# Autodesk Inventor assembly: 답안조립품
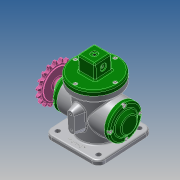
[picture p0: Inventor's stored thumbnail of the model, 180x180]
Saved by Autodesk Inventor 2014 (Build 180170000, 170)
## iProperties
Created: 2021-03
Part Number: 답안조립품
Document SubType Name: Assembly
Designer: kb542
Author: kb542
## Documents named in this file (19)
- C:\Users\kb542\Desktop\710306V1011\답안조립품.iam
- C:\Users\kb542\Desktop\710306V1011\E-링.ipt
- C:\Users\kb542\Desktop\710306V1011\덮개.ipt
- C:\Users\kb542\Desktop\710306V1011\뒤커버.ipt
- C:\Users\kb542\Desktop\710306V1011\링크.ipt
- C:\Users\kb542\Desktop\710306V1011\멈춤나사 M3.ipt
- C:\Users\kb542\Desktop\710306V1011\베어링 17 x 40 x 12.ipt
- C:\Users\kb542\Desktop\710306V1011\본체.ipt
- C:\Users\kb542\Desktop\710306V1011\볼트 M4 x 8.ipt
- C:\Users\kb542\Desktop\710306V1011\볼트 M4 x 10.ipt
- C:\Users\kb542\Desktop\710306V1011\스프로킷.ipt
- C:\Users\kb542\Desktop\710306V1011\슬라이더.ipt
- C:\Users\kb542\Desktop\710306V1011\앞커버.ipt
- C:\Users\kb542\Desktop\710306V1011\오일 실 17 30 8.ipt
- C:\Users\kb542\Desktop\710306V1011\와셔 4x16.ipt
- C:\Users\kb542\Desktop\710306V1011\클레비스 핀 6 x 22.ipt
- 클레비스 핀 6 x 22.ipt
- C:\Users\kb542\Desktop\710306V1011\키 4 x 4 x 12.ipt
- C:\Users\kb542\Desktop\710306V1011\편심축.ipt
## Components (1 placed, 1 different names)
1. E-링:1
